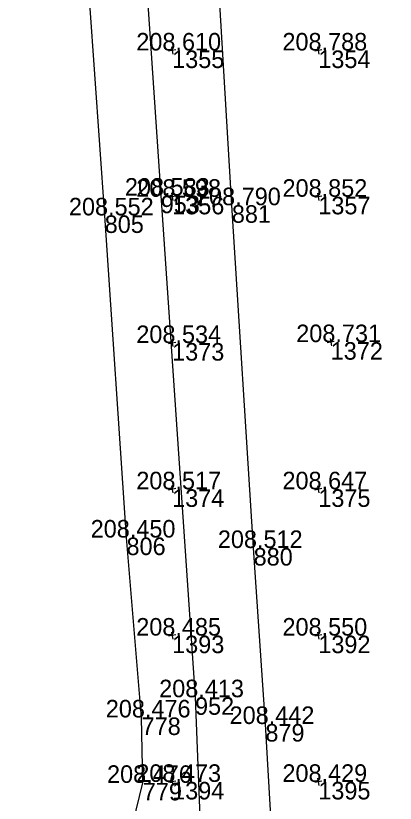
# Model space of a CAD drawing. Extents: x -556590 to -554855, y -1137918 to -1135717.
# Drawn here: x -554980.7 to -554954.7, y -1137601.5 to -1137547.6 of the extents above; entities that cross this region are included whole.
import ezdxf

# ---------------------------------------------------------------- set-up
doc = ezdxf.new("R2010")
doc.units = 0
for name, color, linetype in [('Vrstva 17', 7, 'Continuous'), ('Vrstva 49', 7, 'Continuous'), ('Vrstva 51', 7, 'Continuous'), ('Vrstva 60', 7, 'Continuous'), ('Vrstva 61', 7, 'Continuous')]:
    doc.layers.add(name, color=color, linetype=linetype)

msp = doc.modelspace()

# ---------------------------------------------------------------- linework, layer by layer
at = {"layer": 'Vrstva 17'}
msp.add_line((-554961.94, -1137624.125), (-554963.62, -1137596.043), dxfattribs=at)
msp.add_lwpolyline([(-554963.62, -1137596.043), (-554964.424, -1137584.011), (-554965.915, -1137560.578), (-554966.915, -1137543.736), (-554969.095, -1137508.973), (-554971.191, -1137477.072)], dxfattribs=at)
at = {"layer": 'Vrstva 49'}
for p, q in [((-554969.754, -1137549.953), (-554970.246, -1137550.047)), ((-554970.047, -1137549.754), (-554969.953, -1137550.246)), ((-554959.754, -1137549.953), (-554960.246, -1137550.047)), ((-554960.047, -1137549.754), (-554959.953, -1137550.246)), ((-554969.754, -1137559.953), (-554970.246, -1137560.047)), ((-554970.047, -1137559.754), (-554969.953, -1137560.246)), ((-554959.754, -1137559.953), (-554960.246, -1137560.047)), ((-554960.047, -1137559.754), (-554959.953, -1137560.246)), ((-554969.754, -1137569.953), (-554970.246, -1137570.047)), ((-554970.047, -1137569.754), (-554969.953, -1137570.246)), ((-554958.905, -1137569.89), (-554959.397, -1137569.984)), ((-554959.198, -1137569.691), (-554959.104, -1137570.183)), ((-554970.047, -1137579.754), (-554969.953, -1137580.246)), ((-554960.047, -1137579.754), (-554959.953, -1137580.246)), ((-554969.754, -1137579.953), (-554970.246, -1137580.047)), ((-554959.754, -1137579.953), (-554960.246, -1137580.047)), ((-554969.754, -1137589.953), (-554970.246, -1137590.047)), ((-554970.047, -1137589.754), (-554969.953, -1137590.246)), ((-554959.754, -1137589.953), (-554960.246, -1137590.047)), ((-554960.047, -1137589.754), (-554959.953, -1137590.246)), ((-554970.047, -1137599.754), (-554969.953, -1137600.246)), ((-554960.047, -1137599.754), (-554959.953, -1137600.246)), ((-554969.754, -1137599.953), (-554970.246, -1137600.047)), ((-554959.754, -1137599.953), (-554960.246, -1137600.047))]:
    msp.add_line(p, q, dxfattribs=at)
at = {"layer": 'Vrstva 51'}
for points in [[(-554976.027, -1137608.118), (-554973.798, -1137605.332), (-554972.683, -1137602.879), (-554972.003, -1137600.068), (-554972.088, -1137595.595), (-554973.123, -1137583.295), (-554974.615, -1137561.273), (-554975.973, -1137541.93), (-554977.781, -1137514.038), (-554980.067, -1137478.381), (-554980.702, -1137463.612), (-554980.699, -1137450.714), (-554980.221, -1137439.24)], [(-554973.245, -1137523.715), (-554970.78, -1137559.924), (-554968.435, -1137594.215), (-554967.878, -1137608.256), (-554966.602, -1137627.583), (-554965.306, -1137646.243), (-554964.198, -1137653.564), (-554963.635, -1137655.042), (-554962.366, -1137656.566), (-554960.699, -1137657.787), (-554958.729, -1137658.841), (-554953.644, -1137658.661), (-554941.396, -1137658.222), (-554940.971, -1137661.696), (-554944.152, -1137661.759), (-554958.02, -1137662.297), (-554960.233, -1137662.718), (-554958.252, -1137672.891), (-554957.449, -1137678.239), (-554956.919, -1137684.337), (-554959.937, -1137681.133)]]:
    msp.add_lwpolyline(points, dxfattribs=at)
at = {"layer": 'Vrstva 60'}
for p, q in [((-554970, -1137550), (-554970, -1137550)), ((-554960, -1137550), (-554960, -1137550)), ((-554970.78, -1137559.924), (-554970.78, -1137559.924)), ((-554970, -1137560), (-554970, -1137560)), ((-554960, -1137560), (-554960, -1137560)), ((-554965.915, -1137560.578), (-554965.915, -1137560.578)), ((-554974.615, -1137561.273), (-554974.615, -1137561.273)), ((-554970, -1137570), (-554970, -1137570)), ((-554959.151, -1137569.937), (-554959.151, -1137569.937)), ((-554970, -1137580), (-554970, -1137580)), ((-554960, -1137580), (-554960, -1137580)), ((-554973.123, -1137583.295), (-554973.123, -1137583.295)), ((-554964.424, -1137584.011), (-554964.424, -1137584.011)), ((-554970, -1137590), (-554970, -1137590)), ((-554960, -1137590), (-554960, -1137590)), ((-554968.435, -1137594.215), (-554968.435, -1137594.215)), ((-554972.088, -1137595.595), (-554972.088, -1137595.595)), ((-554963.62, -1137596.043), (-554963.62, -1137596.043)), ((-554972.003, -1137600.068), (-554972.003, -1137600.068)), ((-554970, -1137600), (-554970, -1137600)), ((-554960, -1137600), (-554960, -1137600))]:
    msp.add_line(p, q, dxfattribs=at)

# ---------------------------------------------------------------- texts
for s, p in [('1355', (-554970, -1137551.2)), ('1354', (-554960, -1137551.2)), ('953', (-554970.78, -1137561.124)), ('1356', (-554970, -1137561.2)), ('1357', (-554960, -1137561.2)), ('881', (-554965.915, -1137561.778)), ('805', (-554974.615, -1137562.473)), ('1373', (-554970, -1137571.2)), ('1372', (-554959.151, -1137571.137)), ('1374', (-554970, -1137581.2)), ('1375', (-554960, -1137581.2)), ('806', (-554973.123, -1137584.495)), ('880', (-554964.424, -1137585.211)), ('1393', (-554970, -1137591.2)), ('1392', (-554960, -1137591.2)), ('952', (-554968.435, -1137595.415)), ('778', (-554972.088, -1137596.795)), ('879', (-554963.62, -1137597.243)), ('779', (-554972.003, -1137601.268)), ('1394', (-554970, -1137601.2)), ('1395', (-554960, -1137601.2))]:
    msp.add_text(s, height=1.2, dxfattribs=at).set_placement(p)
at = {"layer": 'Vrstva 61'}
for s, p in [('208.610', (-554972.451, -1137550)), ('208.788', (-554962.454, -1137550)), ('208.583', (-554973.232, -1137559.924)), ('208.598', (-554972.454, -1137560)), ('208.852', (-554962.448, -1137560)), ('208.790', (-554968.366, -1137560.578)), ('208.552', (-554977.063, -1137561.273)), ('208.534', (-554972.451, -1137570)), ('208.731', (-554961.508, -1137569.937)), ('208.517', (-554972.452, -1137580)), ('208.647', (-554962.452, -1137580)), ('208.450', (-554975.574, -1137583.295)), ('208.512', (-554966.872, -1137584.011)), ('208.485', (-554972.456, -1137590)), ('208.550', (-554962.451, -1137590)), ('208.413', (-554970.887, -1137594.215)), ('208.476', (-554974.54, -1137595.595)), ('208.442', (-554966.068, -1137596.043)), ('208.476', (-554974.455, -1137600.068)), ('208.473', (-554972.452, -1137600)), ('208.429', (-554962.454, -1137600))]:
    msp.add_text(s, height=1.2, dxfattribs=at).set_placement(p)

doc.saveas('drawing.dxf')
